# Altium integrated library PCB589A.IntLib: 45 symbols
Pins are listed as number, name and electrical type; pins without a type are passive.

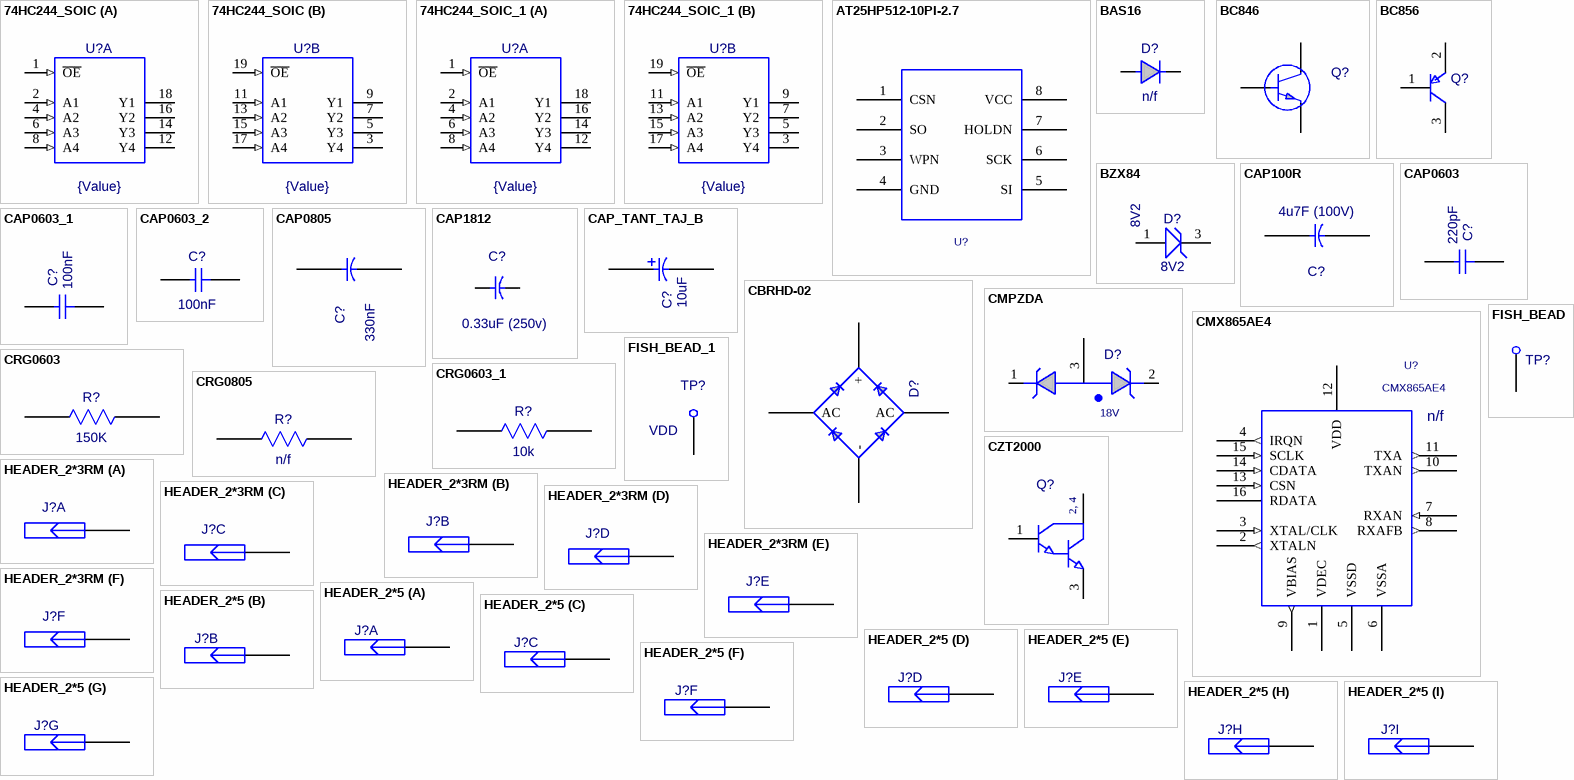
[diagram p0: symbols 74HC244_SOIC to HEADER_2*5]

## 74HC244_SOIC
designator U?  value {Value}
Octal buffer/line driver; 3-state; Part Number: ICS110; OriginalName: M74HC244M1R; ComponentField6: Power pins are hidden; ComponentField7: Published 8-Jun-2000
footprint SO-G20
pins on every part: 10 GND (power) hidden to GND, 20 VCC (power) hidden to VDD
part A pins: 1 ~{OE} (in), 2 A1 (in), 4 A2 (in), 6 A3 (in), 8 A4 (in), 12 Y4 (hiz), 14 Y3 (hiz), 16 Y2 (hiz), 18 Y1 (hiz)
part B pins: 3 Y4 (hiz), 5 Y3 (hiz), 7 Y2 (hiz), 9 Y1 (hiz), 11 A1 (in), 13 A2 (in), 15 A3 (in), 17 A4 (in), 19 ~{OE} (in)

## 74HC244_SOIC_1
designator U?  value {Value}
Octal buffer/line driver; 3-state; Part Number: ICS110; OriginalName: M74HC244M1R; ComponentField6: Power pins are hidden; ComponentField7: Published 8-Jun-2000
footprint SO-G20
pins on every part: 10 GND (power) hidden, 20 VCC (power) hidden
part A pins: 1 ~{OE} (in), 2 A1 (in), 4 A2 (in), 6 A3 (in), 8 A4 (in), 12 Y4 (hiz), 14 Y3 (hiz), 16 Y2 (hiz), 18 Y1 (hiz)
part B pins: 3 Y4 (hiz), 5 Y3 (hiz), 7 Y2 (hiz), 9 Y1 (hiz), 11 A1 (in), 13 A2 (in), 15 A3 (in), 17 A4 (in), 19 ~{OE} (in)

## AT25HP512-10PI-2.7
designator U?
SPI Serial EEPROM 512k; Part Number: {Part Number}; WhenFit: PTH
footprint DIP8_AT25HP512-10PI-2.7()
footprint DIP8
pins: 1 CSN, 2 SO, 3 WPN, 4 GND (power), 5 SI, 6 SCK, 7 HOLDN, 8 VCC (power)

## BAS16
designator D?, comment n/f
Switching diode, surface mount SOT-23; Part Number: DSM022; WhenFit: SMT_Other
footprint SOT23(SDG)_BAS16()
footprint SOT23(SDG)
pins: 1 A, 2 hidden, 3 K

## BC846
designator Q?
NPN general purpose transistor; Part Number: DSM049; WhenFit: SMT_Other
footprint SOT23(SDG)_BC846()
footprint SOT23(SDG)_BC846(Primary)
pins: B base, C collector, E emitter

## BC856
designator Q?
General purpose transistor PNP SMT; Part Number: DSM055; OriginalName: BC856BLT1; ComponentField7: Published 29-Sep-2000; WhenFit: SMT_Other
footprint SOT-23_BC856()
simulation model BC856BLT1
footprint SOT-23
pins: 1 B, 2 E, 3 C

## BZX84
designator D?, comment 8V2
BZX series zener 300mW SMT; Part Number: DSM046; OriginalName: BZX84C10LT1; ComponentField6: Pin 2 is not connected and not drawn.; ComponentField7: Published 29-Sep-2000; WhenFit: SMT_Other
footprint SO-G3/Z3.3_BZX84()
simulation model BZX84C10LT1
footprint SO-G3/Z3.3
pins: 1 A, 3 K

## CAP100R
designator C?, comment 4u7F (100V)
Non-polarised radial capacitor 100 thou pin spacing.; Part Number: CAP053; WhenFit: AWASH
footprint CAP100R_CAP100R()
footprint CAP100R
pins: 1, 2

## CAP0603
designator C?, comment 220pF
SMT capacitor; Part Number: CAP066; WhenFit: SMT_CAP
footprint 0603COM_CAP0603()
footprint 0603COM
pins: 1, 2

## CAP0603_1
designator C?, comment 100nF
SMT capacitor; Part Number: CAP062; WhenFit: SMT_CAP
footprint 0603COM_CAP0603()
footprint 0603COM
pins: 1, 2

## CAP0603_2
designator C?, comment 100nF
SMT capacitor; Part Number: CAP062; WhenFit: {WhenFit}
footprint 0603COM
pins: 1, 2

## CAP0805
designator C?, comment 330nF
SMT capacitor; Part Number: CAP092; WhenFit: SMT_CAP
footprint CC0805_CAP0805()
footprint CC0805
pins: 1, 2

## CAP1812
designator C?, comment 0.33uF (250v)
Generic capacitor, surface mount 1812; Part Number: CAP090; WhenFit: SMT_CAP
footprint CC1812_CAP1812()
footprint CC1812
pins: 1, 2

## CAP_TANT_TAJ_B
designator C?, comment 10uF
TAJ series case code B, SMT tantalum; Part Number: CAP095; WhenFit: SMT_CAP
footprint TC3528P_CAP_TANT_TAJ_B()
footprint TC3528P_CAP_TANT_TAJ_B(Primary)
pins: A +ve, B -ve

## CBRHD-02
designator D?
Central Semiconductor surface mount bridge rectifier, 0.5A; Part Number: DSM029; WhenFit: SMT_Other
footprint SDIP4_CBRHD-02()
footprint SDIP4
pins: 1 +, 2 -, 3 AC, 4 AC

## CMPZDA
designator D?, comment 18V
Dual Zener diode, common anode, SOT-23; Part Number: DSM063; WhenFit: SMT_Other
footprint SOT23(SDG)_CMPZDA()
footprint SOT23(SDG)
pins: 1 C2, 2 C1, 3 A1A2

## CMX865AE4
designator U?  value n/f
Telecom Signalling Device; WhenFit: {WhenFit}
footprint E4_CMX865AE4()
footprint E4
pins: 1 VDEC (power), 2 XTALN (out), 3 XTAL/CLK (in), 4 IRQN (out), 5 VSSD (power), 6 VSSA (power), 7 RXAN (in), 8 RXAFB (out), 9 VBIAS (out), 10 TXAN (out), 11 TXA (out), 12 VDD (power), 13 CSN (in), 14 CDATA (in), 15 SCLK (in), 16 RDATA (hiz)

## CRG0603
designator R?, comment 150K
Generic SMT resistor, 1%.0.1W.; Part Number: RES148; WhenFit: SMT_RES
footprint 0603COM_CRG0603()
footprint 0603COM
pins: 1, 2

## CRG0603_1
designator R?, comment 10k
Generic SMT resistor, 1%.0.1W.; Part Number: RES065; WhenFit: SMT_RES
footprint 0603COM
pins: 1, 2

## CRG0805
designator R?, comment n/f
Generic SMT resistor, 1%.0.125W.; Part Number: RES076; WhenFit: SMT_RES
footprint RC0805_CRG0805()
footprint RC0805
pins: 1, 2

## CZT2000
designator Q?
NPN Darlington 2W SOT223; Part Number: DSM045; OriginalName: FZT605; WhenFit: SMT_Other
footprint DSO-G3/D7_CZT2000()
simulation model FZT605
footprint DSO-G3/D7
pins: 1 B, 2 C, 3 E, 4 C

## FISH_BEAD
designator TP?, comment RXAFB  (value not drawn)
Fish Beads 1.32mm PCB hole; Part Number: CON008; silkscreen label: {silkscreen label}; FitAfterWash: FALSE
footprint FISH_BEAD_FOOT_FISH_BEAD(Primary)
pins: TP 1

## FISH_BEAD_1
designator TP?, comment VDD
Fish Beads 1.32mm PCB hole; Part Number: CON008; WhenFit: PTH
footprint FISH_BEAD_FOOT_FISH_BEAD()
footprint FISH_BEAD_FOOT_FISH_BEAD(Primary)
pins: TP 1

## HEADER_2*3RM
designator J?
3 + 3 double row 0.1in header right angle; Part Number: CON082; WhenFit: PTH
footprint IDC6RM_HEADER_2*3RM()
footprint IDC6RM
part A pins: 1
part B pins: 2
part C pins: 3
part D pins: 4
part E pins: 5
part F pins: 6

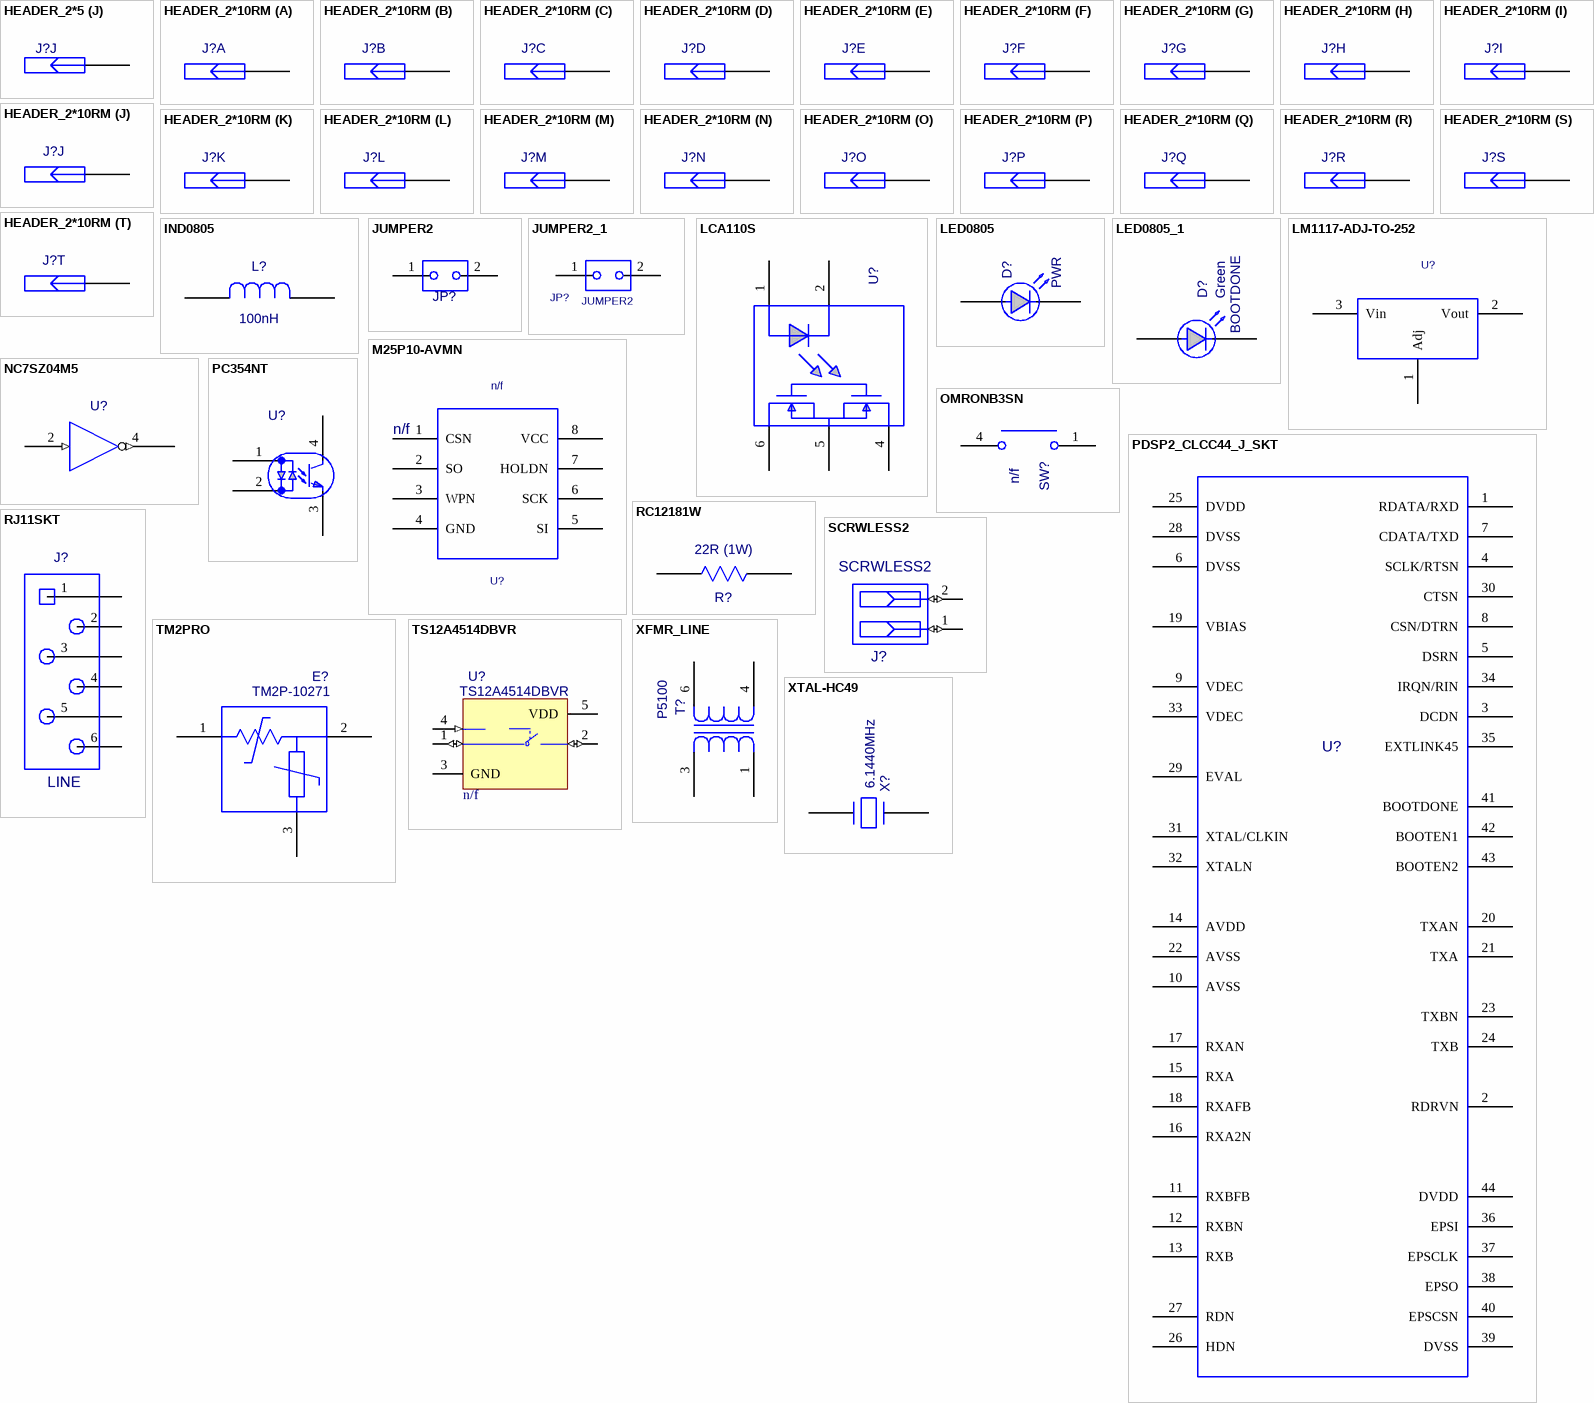
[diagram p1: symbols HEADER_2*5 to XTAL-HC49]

## HEADER_2*5
designator J?, comment n/f  (value not drawn)
10 way, 0.1inch pitch header; Part Number: CON027; WhenFit: PTH
footprint IDC10M_HEADER_2*5()
footprint IDC10M
part A pins: 1 P1
part B pins: 2 P1
part C pins: 3 P1
part D pins: 4 P1
part E pins: 5 P1
part F pins: 6 P1
part G pins: 7 P1
part H pins: 8 P1
part I pins: 9 P1
part J pins: 10 P1

## HEADER_2*10RM
designator J?
10 + 10 double row 0.1in header right angle; Part Number: CON057; WhenFit: PTH
footprint IDC20RM_HEADER_2*10RM()
footprint IDC20RM
part A pins: 1
part B pins: 2
part C pins: 3
part D pins: 4
part E pins: 5
part F pins: 6
part G pins: 7
part H pins: 8
part I pins: 9
part J pins: 10
part K pins: 11
part L pins: 12
part M pins: 13
part N pins: 14
part O pins: 15
part P pins: 16
part Q pins: 17
part R pins: 18
part S pins: 19
part T pins: 20

## IND0805
designator L?, comment 100nH
SMT Inductor; Part Number: TRF003; WhenFit: SMT_Other
footprint RC0805_IND0805()
footprint RC0805
pins: 1, 2

## JUMPER2
designator JP?
PIN HEADER 2X1; Part Number: CON005; WhenFit: PTH
footprint JMP2_JUMPER2()
footprint JMP2
pins: 1, 2

## JUMPER2_1
designator JP?, comment JUMPER2
PIN HEADER 2X1; Part Number: CON005
footprint JMP2
pins: 1, 2

## LCA110S
designator U?
Single pole optoMOS relay; Part Number: ICS034; WhenFit: SMT_Other
footprint SMD6_LCA110S()
footprint SMD6
pins: 1, 2, 3 NC hidden, 4, 5, 6

## LED0805
designator D?, comment PWR
LED, 0805 surface mount; Part Number: OPT005; WhenFit: SMT_Other
footprint LED0805_LED0805()
footprint LED0805
pins: 1 ANODE, 2 CATHODE

## LED0805_1
designator D?, comment BOOTDONE  value Green
LED, 0805 surface mount; Part Number: OPT005
footprint LED0805
pins: 1 ANODE, 2 CATHODE

## LM1117-ADJ-TO-252
designator U?
Part Number: ICS100; WhenFit: SMT_Other
footprint TO-252_LM1117-ADJ-TO-252()
footprint TO-252
pins: 1 Adj, 2 Vout, 3 Vin

## M25P10-AVMN
designator U?, comment n/f
SPI 1Mbit Flash low voltage; Part Number: ICS107; WhenFit: {WhenFit}
footprint SO8_M25P10-AVMN()
footprint SO8
pins: 1 CSN, 2 SO, 3 WPN, 4 GND (power), 5 SI, 6 SCK, 7 HOLDN, 8 VCC (power)

## NC7SZ04M5
designator U?
Tiny Logic single Inverter; Part Number: ICS079; WhenFit: SMT_Other
footprint SOT23-5_NC7SZ04M5()
footprint SOT23-5
pins: 1 hidden, 2 IN (in), 3 GND (power) hidden to GND, 4 OUT (out), 5 VCC (power) hidden to VDD

## OMRONB3SN
designator SW?, comment n/f
Omron B3SN series, low profile, SMT  tactile switch; Part Number: SWI006; WhenFit: AWASH
footprint OMRONB3SN_OMRONB3SN()
footprint OMRONB3SN
pins: 1, 2 hidden, 3 hidden, 4

## PC354NT
designator U?
AC input photocoupler; Part Number: ICS036; WhenFit: SMT_Other
footprint SOP4_PC354NT()
footprint SOP4
pins: 1, 2, 3 e, 4 c

## PDSP2_CLCC44_J_SKT
designator U?
PDSP2 Platform for Telecoms; WhenFit: PTH
footprint PLCCSOCKET44_PDSP2_CLCC44_J_SKT()
footprint PLCCSOCKET44
pins: 1 RDATA/RXD, 2 RDRVN, 3 DCDN, 4 SCLK/RTSN, 5 DSRN, 6 DVSS, 7 CDATA/TXD, 8 CSN/DTRN, 9 VDEC, 10 AVSS, 11 RXBFB, 12 RXBN, 13 RXB, 14 AVDD, 15 RXA, 16 RXA2N, 17 RXAN, 18 RXAFB, 19 VBIAS, 20 TXAN, 21 TXA, 22 AVSS, 23 TXBN, 24 TXB, 25 DVDD, 26 HDN, 27 RDN, 28 DVSS, 29 EVAL, 30 CTSN, 31 XTAL/CLKIN, 32 XTALN, 33 VDEC, 34 IRQN/RIN, 35 EXTLINK45, 36 EPSI, 37 EPSCLK, 38 EPSO, 39 DVSS, 40 EPSCSN, 41 BOOTDONE, 42 BOOTEN1, 43 BOOTEN2, 44 DVDD

## RC12181W
designator R?, comment 22R (1W)
Philips Components 1W, SMT 1218  resistor; Part Number: RES150; WhenFit: SMT_RES
footprint RC12181WA_RC12181W()
footprint RC12181WA
pins: 1, 2

## RJ11SKT
designator J?, comment LINE
RJ11 telephone socket; Part Number: CON014; WhenFit: PTH
footprint RJ11SKT_RJ11SKT()
footprint RJ11SKT_RJ11SKT(Primary)
pins: 1, 2, 3, 4, 5, 6, dummy1 hidden, dummy2 hidden

## SCRWLESS2
designator J?
2-way Screwless Terminal Block; Part Number: CON083; Value: Rapid 21-2626
footprint SCRWLESS_2
pins: 1 (io), 2 (io)

## TM2PRO
designator E?, comment TM2P-10271
2Pro Integrated overcurrent/overvoltage protection device; Part Number: FUS003; WhenFit: PTH
footprint TM2PRO_TM2PRO()
footprint TM2PRO
pins: 1, 2, 3

## TS12A4514DBVR
designator U?  value n/f
TI, SPST, CMOS analogue switch, surface mount SOT23-5; Part Number: ICS124; WhenFit: {WhenFit}
footprint SOT23-5
pins: 1 COM (io), 2 NO (io), 3 GND (power), 4 IN (in), 5 VDD (power)

## XFMR_LINE
designator T?, comment P5100
600R line transformer; Part Number: TRF024; WhenFit: AWASH
footprint LINEXFMR_XFMR_LINE()
footprint LINEXFMR_XFMR_LINE(Primary)
pins: 1, 3, 4, 6

## XTAL-HC49
designator X?, comment 6.1440MHz
HC49 Xtal; Part Number: XTL022; WhenFit: AWASH
footprint HC49_XTAL-HC49()
footprint HC49
pins: 1, 2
